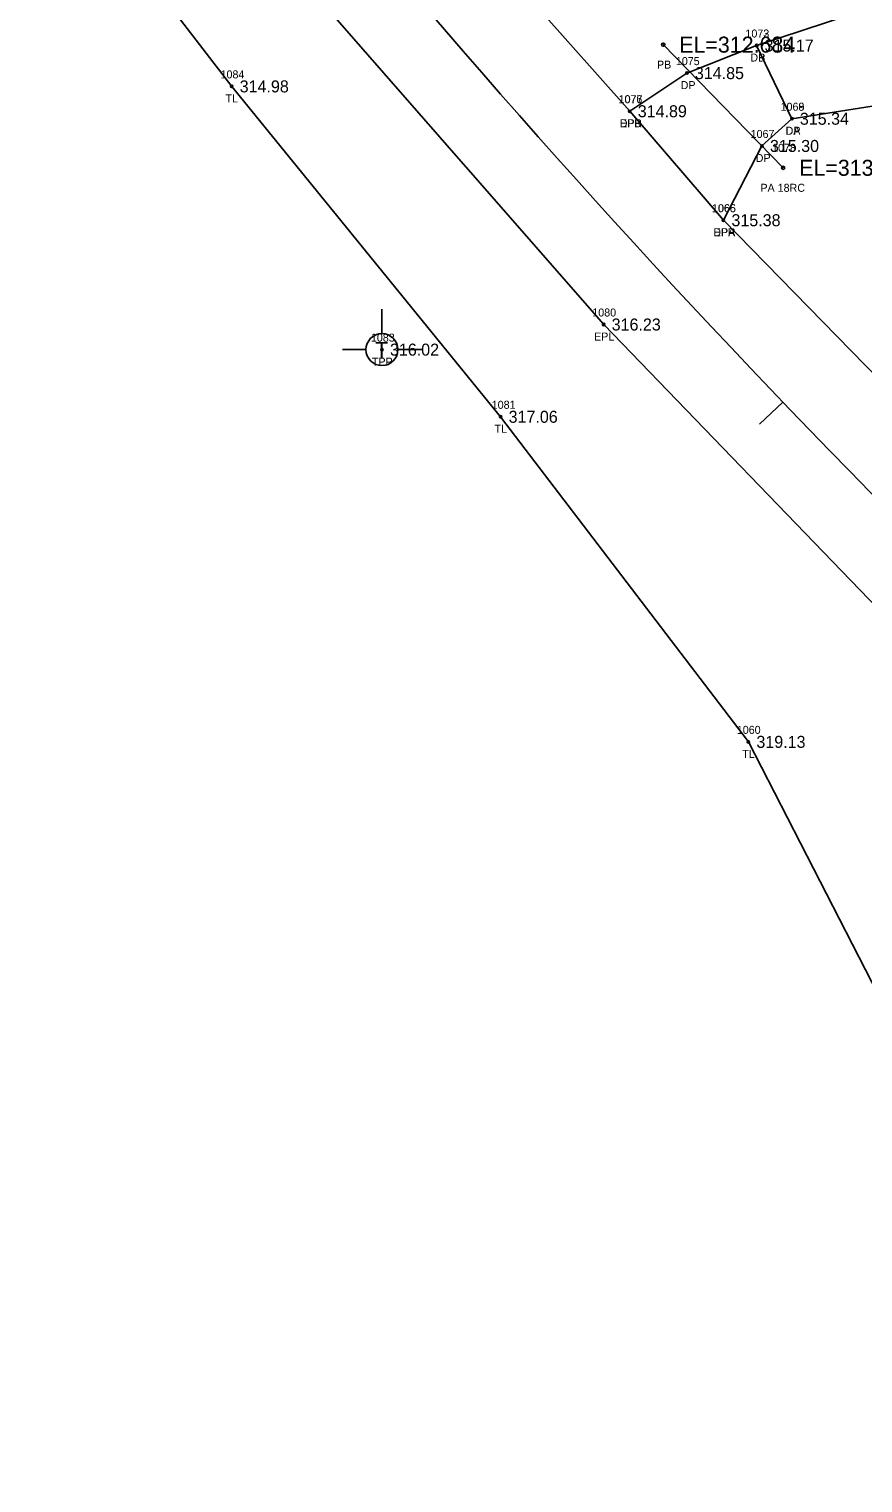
# Model space of a CAD drawing. Extents: x 1865045 to 1867370, y 910391 to 914218.
# Drawn here: x 1866620.1 to 1866724.3, y 910392.9 to 910574.6 of the extents above; entities that cross this region are included whole.
import ezdxf

# ---------------------------------------------------------------- set-up
doc = ezdxf.new("R2010")
doc.units = 0
for name, color, linetype in [('RD_EX_DR_Pipe', 7, 'Continuous'), ('RD_EX_DR_Pipe_txCode', 7, 'Continuous'), ('RD_EX_Driveway', 7, 'Continuous'), ('RD_EX_Driveway_txCode', 7, 'Continuous'), ('RD_EX_Road', 7, 'Continuous'), ('RD_EX_Road_txCode', 7, 'Continuous'), ('RD_EX_TX_Driveway_ELEV', 7, 'Continuous'), ('RD_EX_TX_Road_ELEV', 7, 'Continuous'), ('RD_EX_TX_UT_ELEV', 7, 'Continuous'), ('RD_EX_TX_VEG_ELEV', 7, 'Continuous'), ('RD_EX_UT', 7, 'Continuous'), ('RD_EX_UT_txCode', 7, 'Continuous'), ('RD_EX_VEG', 7, 'Continuous'), ('RD_EX_VEG_txCode', 7, 'Continuous'), ('RD_HC_Cl', 7, 'Continuous'), ('RD_HC_Data_Tic', 7, 'Continuous'), ('RD_SMD_Locator', 7, 'Continuous'), ('RD_TX_Pipe_ElevEX', 7, 'Continuous')]:
    doc.layers.add(name, color=color, linetype=linetype)

msp = doc.modelspace()

# ---------------------------------------------------------------- linework, layer by layer
at = {"layer": 'RD_EX_DR_Pipe'}
msp.add_line((1866714.33, 910557.26), (1866699.34, 910572.65), dxfattribs=at)
at = {"layer": 'RD_EX_Driveway'}
for p, q in [((1866764.08, 910590.14), (1866711.01, 910572.54)), ((1866715.42, 910563.39), (1866765.65, 910571.34))]:
    msp.add_line(p, q, dxfattribs=at)
msp.add_lwpolyline([(1866706.87, 910550.71), (1866711.68, 910559.99), (1866715.42, 910563.39), (1866711.01, 910572.54), (1866702.3, 910569.09), (1866695.16, 910564.33)], dxfattribs=at)
at = {"layer": 'RD_EX_Road'}
for points in [[(1866813.99, 910446.88), (1866778.44, 910479.3), (1866742.34, 910514.45), (1866706.87, 910550.71), (1866695.16, 910564.33), (1866672.6, 910589.75), (1866641.04, 910629.03), (1866609.7, 910670.28), (1866582.23, 910711.25), (1866556.44, 910754.58), (1866532.04, 910798.87), (1866507.56, 910846.03), (1866483.5, 910895.43), (1866461.16, 910941.96), (1866414.86, 911037.95), (1866406.11, 911034.1)], [(1866800.58, 910432.45), (1866764.32, 910465.74), (1866727.39, 910500.95), (1866691.9, 910537.68), (1866657.44, 910577.07), (1866624.97, 910617.36), (1866593.69, 910658.89), (1866565.16, 910701.48), (1866538.98, 910745.57), (1866531.34, 910758.5), (1866513.94, 910791.05), (1866489.48, 910838.44), (1866465.73, 910886.02), (1866443.47, 910933.62), (1866397.5, 911029.82), (1866406.11, 911034.1)]]:
    msp.add_lwpolyline(points, dxfattribs=at)
at = {"layer": 'RD_EX_UT'}
for p, q in [((1866664.19, 910539.61), (1866664.19, 910536.54)), ((1866659.26, 910534.55), (1866662.19, 910534.55)), ((1866666.19, 910534.55), (1866669.26, 910534.55))]:
    msp.add_line(p, q, dxfattribs=at)
msp.add_circle((1866664.19, 910534.54), 2, dxfattribs=at)
at = {"layer": 'RD_EX_VEG'}
msp.add_lwpolyline([(1866770.74, 910392.93), (1866734.38, 910438.07), (1866709.99, 910485.53), (1866679.02, 910526.15), (1866645.41, 910567.43), (1866612.91, 910609.64), (1866580.57, 910649.92), (1866452.86, 910898.44)], dxfattribs=at)
at = {"layer": 'RD_HC_Cl'}
msp.add_arc((1867567.42, 911345.48), 1181.58, 205.67399, 227.8297, dxfattribs=at)
at = {"layer": 'RD_HC_Data_Tic'}
msp.add_line((1866714.28, 910527.99), (1866711.39, 910525.23), dxfattribs=at)
at = {"layer": 'RD_SMD_Locator'}
for centre, radius in [((1866699.34, 910572.65), 0.2), ((1866711.01, 910572.54), 0.15), ((1866711.01, 910572.54), 0.15), ((1866702.3, 910569.09), 0.15), ((1866645.41, 910567.43), 0.15), ((1866695.16, 910564.33), 0.15), ((1866695.16, 910564.33), 0.15), ((1866715.42, 910563.39), 0.15), ((1866715.42, 910563.39), 0.15), ((1866711.68, 910559.99), 0.15), ((1866714.33, 910557.26), 0.2), ((1866706.87, 910550.71), 0.15), ((1866706.87, 910550.71), 0.15), ((1866691.9, 910537.68), 0.15), ((1866664.19, 910534.54), 0.15), ((1866679.02, 910526.15), 0.15), ((1866709.99, 910485.53), 0.15)]:
    msp.add_circle(centre, radius, dxfattribs=at)

# ---------------------------------------------------------------- texts
at = {"layer": 'RD_EX_DR_Pipe_txCode'}
for s, p in [('PB', (1866698.56, 910569.65)), ('1078', (1866712.95, 910559.26)), ('PA 18RC', (1866711.49, 910554.26))]:
    msp.add_text(s, height=1, dxfattribs=at).set_placement(p)
at = {"layer": 'RD_EX_Driveway_txCode'}
for s, p in [('1072', (1866709.62, 910573.54)), ('1073', (1866709.62, 910573.54)), ('DB', (1866710.23, 910570.54)), ('DP', (1866710.23, 910570.54)), ('1075', (1866700.92, 910570.09)), ('DP', (1866701.52, 910567.09)), ('1077', (1866693.78, 910565.33)), ('1068', (1866714.01, 910564.39)), ('1069', (1866714.01, 910564.39)), ('DPB', (1866693.91, 910562.33)), ('DA', (1866714.62, 910561.39)), ('DP', (1866714.64, 910561.39)), ('1067', (1866710.27, 910560.99)), ('DP', (1866710.9, 910557.99)), ('1066', (1866705.43, 910551.71)), ('DPA', (1866705.6, 910548.71))]:
    msp.add_text(s, height=1, dxfattribs=at).set_placement(p)
at = {"layer": 'RD_EX_Road_txCode'}
for s, p in [('1076', (1866693.75, 910565.33)), ('EPR', (1866693.93, 910562.33)), ('1065', (1866705.46, 910551.71)), ('EPR', (1866705.64, 910548.71)), ('1080', (1866690.48, 910538.68)), ('EPL', (1866690.7, 910535.68))]:
    msp.add_text(s, height=1, dxfattribs=at).set_placement(p)
at = {"layer": 'RD_EX_TX_Driveway_ELEV'}
for s, p in [('315.17', (1866712.01, 910571.79)), ('315.17', (1866712.01, 910571.79)), ('314.85', (1866703.3, 910568.34)), ('314.89', (1866696.16, 910563.58)), ('315.34', (1866716.42, 910562.64)), ('315.34', (1866716.42, 910562.64)), ('315.30', (1866712.68, 910559.24)), ('315.38', (1866707.87, 910549.96))]:
    msp.add_text(s, height=1.5, dxfattribs=at).set_placement(p)
at = {"layer": 'RD_EX_TX_Road_ELEV'}
for s, p in [('314.89', (1866696.16, 910563.58)), ('315.38', (1866707.87, 910549.96)), ('316.23', (1866692.9, 910536.93))]:
    msp.add_text(s, height=1.5, dxfattribs=at).set_placement(p)
at = {"layer": 'RD_EX_TX_UT_ELEV'}
msp.add_text('316.02', height=1.5, dxfattribs=at).set_placement((1866665.19, 910533.79))
at = {"layer": 'RD_EX_TX_VEG_ELEV'}
for s, p in [('314.98', (1866646.41, 910566.68)), ('317.06', (1866680.02, 910525.4)), ('319.13', (1866710.99, 910484.78))]:
    msp.add_text(s, height=1.5, dxfattribs=at).set_placement(p)
at = {"layer": 'RD_EX_UT'}
msp.add_text('T', height=2, dxfattribs=at).set_placement((1866663.34, 910533.49))
at = {"layer": 'RD_EX_UT_txCode'}
for s, p in [('1083', (1866662.81, 910535.54)), ('TPP', (1866662.93, 910532.54))]:
    msp.add_text(s, height=1, dxfattribs=at).set_placement(p)
at = {"layer": 'RD_EX_VEG_txCode'}
for s, p in [('1084', (1866644.02, 910568.43)), ('TL', (1866644.64, 910565.43)), ('1081', (1866677.91, 910527.15)), ('TL', (1866678.25, 910524.15)), ('1060', (1866708.54, 910486.53)), ('TL', (1866709.22, 910483.53))]:
    msp.add_text(s, height=1, dxfattribs=at).set_placement(p)
at = {"layer": 'RD_TX_Pipe_ElevEX'}
for s, p in [('EL=312.684', (1866701.34, 910571.65)), ('EL=313.076', (1866716.33, 910556.26))]:
    msp.add_text(s, height=2, dxfattribs=at).set_placement(p)

doc.saveas('drawing.dxf')
